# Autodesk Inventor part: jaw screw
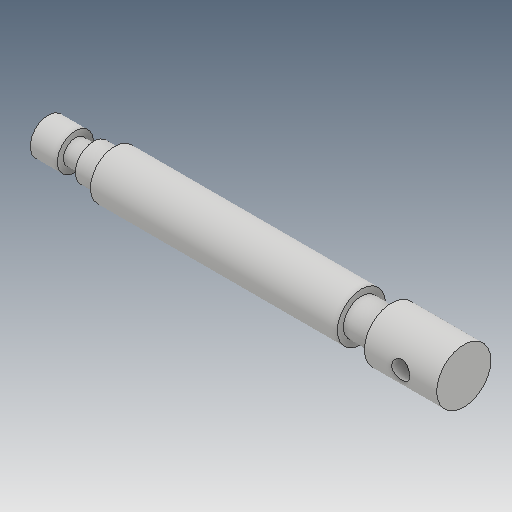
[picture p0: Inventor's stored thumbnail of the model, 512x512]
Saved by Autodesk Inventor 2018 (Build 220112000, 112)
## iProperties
Created: 2016-03
Part Number: jaw screw
Material: Generic
Document SubType Name: Modeling
Designer: Sandeep
Density: 1 g/cm^3
Appearance: Default
Mass: 25.5852 g
Surface Area: 75.8462 cm^2
Volume: 25.5852 cm^3
Author: Sandeep
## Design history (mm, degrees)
sketch "Sketch1"
  geometry: L1 (0, -138)-(-6, -138); L2 (-6, -116)-(-6, -116); L3 (-6, -116)-(-8, -116); L4 (-8, -116)-(-8, -34); L5 (-8, -34)-(-6, -34); L6 (-6, -34)-(-6, -24); L7 (-6, -24)-(-9, -24); L8 (-9, -24)-(-9, 0); L9 (-9, 0)-(0, 0); L10 (0, 0)-(0, -138); L11 (0, 0)-(0, 14.581); L12 (-6, -116)-(-6, -123); L13 (-6, -123)-(-4, -123); L14 (-4, -123)-(-4, -129); L15 (-4, -129)-(-6, -129); L16 (-6, -129)-(-6, -138); 1 other entity
  constraints: 32 end point, 10 perpendicular, 3 point on line, 3 vertical, 1 coincident, 1 horizontal, 2 other
  dimensions: "d0" = 18 diameter of L8 L11; "d1" = 12 diameter of L6 L11; "d3" = 24 distance of L7.end L8.end; "d4" = 10 distance of L5.end L6.end; "d5" = 82 distance of L3.end L4.end; "d6" = 138 distance between parallel lines of L1 L9; "d8" = 16 diameter of L4 L11; "d10" = 6 distance of L13.end L14.end; "d11" = 9 distance of L15.end L1.end; "d12" = 8 diameter of L14 L11
revolve "Revolution1" sketch "Sketch1" stored, may be unused: angle "d9" = 90 deg
sketch "Sketch2"
  geometry: L1 (0, -9)-(0, 9) reference; L2 (0, 0)-(-20.975, 0); C1 r 3 at (-12, 0)
  constraints: 2 end point, 1 centre point, 1 horizontal, 1 point on line
  dimensions: "d13" = 6 diameter of C1; "d14" = 12 distance from line of L1 C1.centre
extrude "Extrusion1" cut sketch "Sketch2" distance "d15" = 25; taper "d16" = 0 deg
body "Solid1"
